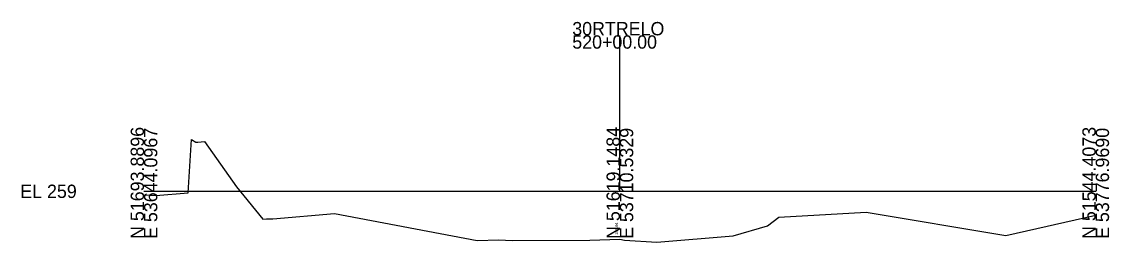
# Model space of a CAD drawing. Extents: x 12366 to 12594, y 96215 to 100251.
# Drawn here: x 12365.6 to 12594.1, y 98214 to 98260.2 of the extents above; entities that cross this region are included whole.
import ezdxf

# ---------------------------------------------------------------- set-up
doc = ezdxf.new("R2010")
doc.units = 0
for name, color, linetype in [('Level 10', 7, 'Continuous'), ('Level 60', 7, 'Continuous'), ('Level 63', 7, 'Continuous')]:
    doc.layers.add(name, color=color, linetype=linetype)

msp = doc.modelspace()

# ---------------------------------------------------------------- linework, layer by layer
at = {"layer": 'Level 60'}
for p, q in [((12400.55, 98224.34), (12401.27, 98235.55)), ((12401.27, 98235.55), (12402.21, 98234.93)), ((12402.21, 98234.93), (12402.63, 98234.93)), ((12402.63, 98234.93), (12404, 98235.09)), ((12404, 98235.09), (12410.73, 98225.55)), ((12393.76, 98223.73), (12400.55, 98224.34)), ((12410.73, 98225.55), (12416.3, 98218.81)), ((12391.3, 98223.89), (12393.76, 98223.73)), ((12418.38, 98218.83), (12431.3, 98220)), ((12431.3, 98220), (12461.3, 98214.31)), ((12524.7, 98219.24), (12543.03, 98220.29)), ((12543.03, 98220.29), (12572.39, 98215.39)), ((12572.39, 98215.39), (12591.3, 98219.66)), ((12416.3, 98218.81), (12417.07, 98218.86)), ((12417.07, 98218.86), (12418.38, 98218.83)), ((12515.14, 98215.32), (12522.33, 98217.38)), ((12522.33, 98217.38), (12524.7, 98219.24)), ((12499.1, 98213.95), (12515.14, 98215.32)), ((12461.3, 98214.31), (12465.86, 98214.45)), ((12465.86, 98214.45), (12468.66, 98214.32)), ((12468.66, 98214.32), (12485.01, 98214.4)), ((12485.01, 98214.4), (12491.3, 98214.58)), ((12491.3, 98214.58), (12492.25, 98214.37)), ((12492.25, 98214.37), (12499.1, 98213.95))]:
    msp.add_line(p, q, dxfattribs=at)
at = {"layer": 'Level 63'}
for p, q in [((12491.3, 98224.64), (12491.3, 98257.38)), ((12391.3, 98224.64), (12491.3, 98224.64)), ((12491.3, 98224.64), (12591.3, 98224.64))]:
    msp.add_line(p, q, dxfattribs=at)

# ---------------------------------------------------------------- texts
at = {"layer": 'Level 10'}
msp.add_text('248.94', height=0.6, rotation=90, dxfattribs=at).set_placement((12490.9, 98215.58))
at = {"layer": 'Level 63'}
for s, p in [('30RTRELO', (12481.3, 98257.38)), ('520+00.00', (12481.3, 98254.58)), ('EL 259', (12365.3, 98223.24))]:
    msp.add_text(s, height=2.8, dxfattribs=at).set_placement(p)
for s, p in [('N 51693.8896', (12391.3, 98214.64)), ('E 53644.0967', (12394.1, 98214.64)), ('N 51619.1484', (12491.3, 98214.64)), ('E 53710.5329', (12494.1, 98214.64)), ('N 51544.4073', (12591.3, 98214.64)), ('E 53776.9690', (12594.1, 98214.64))]:
    msp.add_text(s, height=2.8, rotation=90, dxfattribs=at).set_placement(p)

doc.saveas('drawing.dxf')
